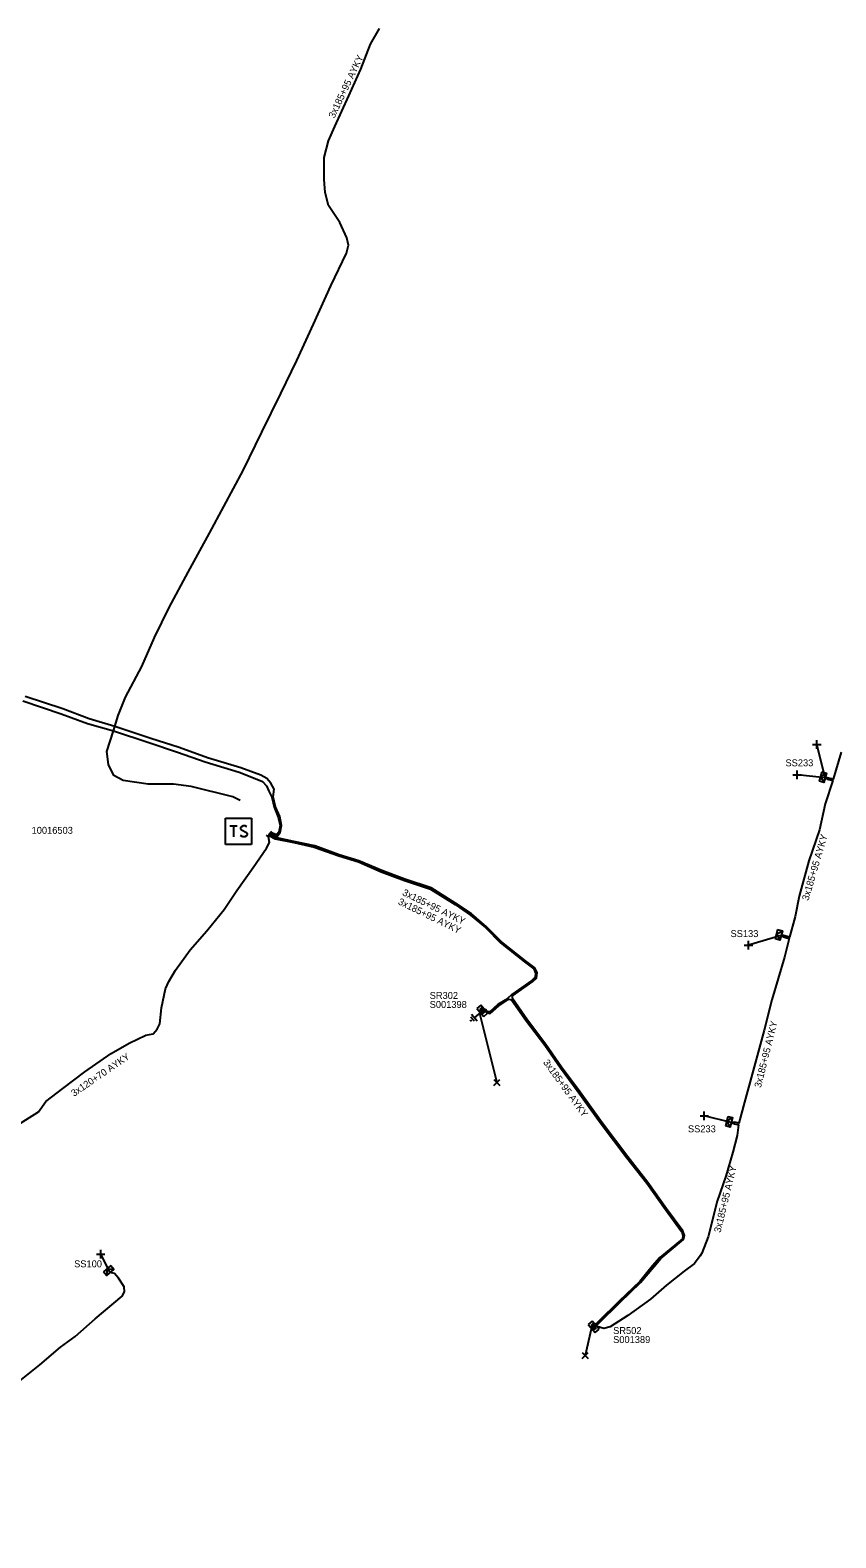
# Model space of a CAD drawing. Extents: x -763093 to -760976, y -1155572 to -1152009.
# Drawn here: x -762242.1 to -762125.9, y -1155258.8 to -1155041.4 of the extents above; entities that cross this region are included whole.
import ezdxf

# ---------------------------------------------------------------- set-up
doc = ezdxf.new("R2010")
doc.units = 0
for name, color, linetype in [('Vrstva 1', 7, 'Continuous'), ('Vrstva 14', 7, 'Continuous'), ('Vrstva 15', 7, 'Continuous'), ('Vrstva 25', 7, 'Continuous'), ('Vrstva 26', 7, 'Continuous'), ('Vrstva 28', 7, 'Continuous'), ('Vrstva 29', 7, 'Continuous'), ('Vrstva 30', 7, 'Continuous'), ('Vrstva 31', 7, 'Continuous'), ('Vrstva 33', 7, 'Continuous'), ('Vrstva 34', 7, 'Continuous'), ('Vrstva 5', 7, 'Continuous'), ('Vrstva 59', 7, 'Continuous'), ('Vrstva 6', 7, 'Continuous'), ('Vrstva 8', 7, 'Continuous'), ('Vrstva 9', 7, 'Continuous')]:
    doc.layers.add(name, color=color, linetype=linetype)

# ---------------------------------------------------------------- blocks, each defined once
blk = doc.blocks.new('NN800')
at = {"layer": 'Vrstva 1'}
for points in [[(-0.44, 0.44), (0.44, -0.44)], [(-0.44, -0.44), (0.44, 0.44)]]:
    blk.add_lwpolyline(points, dxfattribs=at)
blk = doc.blocks.new('NN620')
at = {"layer": 'Vrstva 8'}
for points in [[(0.75, 0), (-0.75, 0)], [(-0.75, 0), (-0.75, -0.75)], [(0.75, -0.75), (0.75, 0)], [(-0.75, -0.75), (0.75, -0.75)], [(0.37, -0.18), (-0.38, -0.18)], [(-0.38, -0.18), (-0.38, -0.56)], [(-0.38, -0.56), (0.37, -0.56)], [(0.32, -0.23), (-0.33, -0.23)], [(-0.33, -0.23), (-0.33, -0.51)], [(-0.33, -0.51), (0.32, -0.51)], [(0.27, -0.27), (-0.28, -0.27)], [(-0.28, -0.27), (-0.28, -0.46)], [(-0.28, -0.46), (0.27, -0.46)], [(0.23, -0.32), (-0.23, -0.32)], [(-0.23, -0.32), (-0.23, -0.42)], [(-0.23, -0.42), (0.23, -0.42)], [(-0.19, -0.37), (0.19, -0.37)], [(0.23, -0.42), (0.23, -0.32)], [(0.27, -0.46), (0.27, -0.27)], [(0.32, -0.51), (0.32, -0.23)], [(0.37, -0.56), (0.37, -0.18)]]:
    blk.add_lwpolyline(points, dxfattribs=at)
blk = doc.blocks.new('NN630')
at = {"layer": 'Vrstva 9'}
for points in [[(0, -0.7), (-0.7, 0)], [(-0.7, -0.7), (-0.7, 0), (0.7, 0), (0.7, -0.7)], [(-0.7, -0.7), (0.7, -0.7)], [(0, -0.7), (0.7, 0)]]:
    blk.add_lwpolyline(points, dxfattribs=at)
blk = doc.blocks.new('NN810')
at = {"layer": 'Vrstva 14'}
for points in [[(0.63, -1.89), (-0.62, -1.89)], [(0, -0.64), (0, -1.89)], [(0.39, -2.2), (-0.4, -2.2)], [(0, -2.52), (-0.12, -2.52)], [(0.14, -2.52), (0, -2.52)]]:
    blk.add_lwpolyline(points, dxfattribs=at)
blk = doc.blocks.new('NN640')
at = {"layer": 'Vrstva 6'}
for points in [[(-1.89, 1.89), (1.89, 1.89)], [(-1.89, -1.89), (-1.89, 1.89)], [(-1.26, 0.79), (-0.22, 0.79)], [(-0.73, 0.79), (-0.73, -0.79)], [(1.2, 0.66), (0.94, 0.79), (0.66, 0.79), (0.41, 0.66), (0.28, 0.47), (0.28, 0.41), (0.41, 0.22), (1.13, -0.16), (1.26, -0.32), (1.26, -0.47), (1.13, -0.66), (0.91, -0.79), (0.63, -0.79), (0.5, -0.73), (0.28, -0.6)], [(1.89, 1.89), (1.89, -1.89)], [(1.89, -1.89), (-1.89, -1.89)]]:
    blk.add_lwpolyline(points, dxfattribs=at)

msp = doc.modelspace()

# ---------------------------------------------------------------- linework, layer by layer
at = {"layer": 'Vrstva 5'}
for points in [[(-762211.82, -1155152.47), (-762212.89, -1155151.97), (-762218.88, -1155150.49), (-762221.47, -1155150.15), (-762225.1, -1155150.14), (-762228.69, -1155149.59), (-762230.04, -1155148.88), (-762230.84, -1155147.3), (-762231.04, -1155145.45), (-762230.08, -1155142.45), (-762229.93, -1155141.84), (-762229.45, -1155140.25), (-762228.38, -1155137.61), (-762226, -1155133.18), (-762224.2, -1155128.99), (-762222.06, -1155124.69), (-762219.32, -1155119.56), (-762216.24, -1155113.95), (-762214.17, -1155110.1), (-762211.4, -1155104.92), (-762208.69, -1155099.41), (-762205.98, -1155093.83), (-762203.67, -1155089.06), (-762201.24, -1155083.82), (-762198.77, -1155078.31), (-762196.49, -1155073.58), (-762196.24, -1155072.42), (-762196.48, -1155071.38), (-762197.47, -1155069.16), (-762199.12, -1155066.71), (-762199.59, -1155064.85), (-762199.74, -1155062.95), (-762199.71, -1155059.79), (-762199.09, -1155057.42), (-762198.17, -1155055.31), (-762196.17, -1155050.9), (-762194.45, -1155047.06), (-762193.03, -1155043.48), (-762191.74, -1155041.22)], [(-762243.18, -1155138.13), (-762237.64, -1155139.99), (-762233.83, -1155141.41), (-762230.08, -1155142.45), (-762225, -1155144.14), (-762220.89, -1155145.51), (-762216.86, -1155146.94), (-762212, -1155148.43), (-762209.19, -1155149.49), (-762208.61, -1155149.77), (-762208.04, -1155150.37), (-762207.68, -1155151.13), (-762207.26, -1155152.02), (-762206.92, -1155153.46), (-762206.34, -1155154.87), (-762206.06, -1155156.11), (-762206.25, -1155157.04), (-762206.6, -1155157.46), (-762207.18, -1155157.18), (-762207.42, -1155156.94)], [(-762207.57, -1155157.07), (-762207.33, -1155157.32), (-762206.54, -1155157.71), (-762206.07, -1155157.12), (-762205.86, -1155156.11), (-762206.14, -1155154.81), (-762206.72, -1155153.4), (-762207.06, -1155151.98), (-762206.95, -1155150.86), (-762207.4, -1155150.01), (-762208, -1155149.34), (-762208.87, -1155148.82), (-762211.76, -1155147.78), (-762216.57, -1155146.33), (-762220.62, -1155144.84), (-762224.71, -1155143.54), (-762229.93, -1155141.84), (-762233.63, -1155140.74), (-762237.43, -1155139.29), (-762242.84, -1155137.5)], [(-762125.19, -1155145.52), (-762126.31, -1155149.4), (-762127.13, -1155149.21), (-762127.47, -1155149.22), (-762127.18, -1155149.4), (-762126.37, -1155149.6), (-762127.47, -1155152.97), (-762128.3, -1155156.7), (-762129.84, -1155161.17), (-762131.25, -1155166.26), (-762131.81, -1155169.22), (-762132.62, -1155172.18), (-762133.5, -1155171.95), (-762133.85, -1155171.95), (-762133.54, -1155172.15), (-762132.67, -1155172.38), (-762133.34, -1155175.08), (-762135.18, -1155181.21), (-762136.26, -1155185.61), (-762137.85, -1155191.4), (-762139.1, -1155196), (-762139.94, -1155199.02), (-762140.51, -1155198.87), (-762141.03, -1155198.89), (-762140.54, -1155199.08), (-762139.98, -1155199.22), (-762140.18, -1155200.76), (-762140.81, -1155203.17), (-762141.81, -1155206.65), (-762143.06, -1155210.25), (-762144.35, -1155215.4), (-762145.25, -1155217.74), (-762145.5, -1155218.13), (-762146.34, -1155219.24), (-762147.84, -1155220.33), (-762150.37, -1155222.34), (-762152.68, -1155224.37), (-762155.93, -1155226.71), (-762158.5, -1155228.35), (-762159.41, -1155228.61), (-762160.34, -1155228.32)], [(-762245.5, -1155200.25), (-762240.9, -1155197.35), (-762239.87, -1155195.89), (-762237.41, -1155193.99), (-762234.23, -1155191.62), (-762230.44, -1155188.98), (-762227.83, -1155187.46), (-762225.42, -1155186.31), (-762224.4, -1155186.11), (-762223.79, -1155185.45), (-762223.4, -1155184.68), (-762223.2, -1155182.37), (-762222.6, -1155179.64), (-762222.11, -1155178.59), (-762221.16, -1155176.93), (-762219.05, -1155174), (-762216.63, -1155171.27), (-762214.16, -1155168.19), (-762212.34, -1155165.48), (-762209.95, -1155162.16), (-762208.03, -1155159.36), (-762207.61, -1155158.56), (-762207.75, -1155157.74), (-762208.02, -1155157.47)], [(-762207.8, -1155157.41), (-762207.61, -1155157.6), (-762206.77, -1155158.03), (-762204.12, -1155158.55), (-762201.15, -1155159.22), (-762197.63, -1155160.48), (-762194.77, -1155161.35), (-762191.49, -1155162.77), (-762188.14, -1155164.03), (-762184.39, -1155165.25), (-762180.83, -1155167.5), (-762178.61, -1155169), (-762176.48, -1155170.82), (-762174.3, -1155173.01), (-762170.83, -1155175.76), (-762169.49, -1155176.75), (-762169.23, -1155177.36), (-762169.31, -1155177.98), (-762169.77, -1155178.43), (-762172.66, -1155180.45), (-762173.28, -1155181.03), (-762173.28, -1155181.06), (-762174.67, -1155181.91), (-762175.86, -1155182.96), (-762176.2, -1155182.89), (-762176.53, -1155182.55)], [(-762160.47, -1155228.15), (-762160.13, -1155227.85), (-762157.04, -1155224.81), (-762154.09, -1155221.96), (-762152.21, -1155219.69), (-762151.19, -1155218.53), (-762147.9, -1155215.75), (-762147.79, -1155215.22), (-762148.02, -1155214.54), (-762150.36, -1155211.33), (-762153.05, -1155207.55), (-762155.92, -1155203.87), (-762159.64, -1155198.97), (-762163.07, -1155194.18), (-762165.48, -1155190.93), (-762167.77, -1155187.65), (-762170.39, -1155184.16), (-762172.57, -1155181.05), (-762172.59, -1155180.64), (-762169.65, -1155178.59), (-762169.13, -1155178.08), (-762169.03, -1155177.34), (-762169.33, -1155176.63), (-762170.71, -1155175.6), (-762174.16, -1155172.87), (-762176.34, -1155170.68), (-762178.49, -1155168.84), (-762180.73, -1155167.34), (-762184.31, -1155165.07), (-762188.08, -1155163.85), (-762191.41, -1155162.59), (-762194.71, -1155161.17), (-762197.57, -1155160.3), (-762201.09, -1155159.02), (-762204.1, -1155158.38), (-762206.72, -1155157.84), (-762207.47, -1155157.46), (-762207.69, -1155157.24)], [(-762176.68, -1155182.69), (-762176.3, -1155183.07), (-762175.8, -1155183.18), (-762174.55, -1155182.07), (-762173.09, -1155181.14), (-762172.7, -1155181.21), (-762170.55, -1155184.28), (-762167.93, -1155187.77), (-762165.64, -1155191.05), (-762163.23, -1155194.3), (-762159.8, -1155199.09), (-762156.08, -1155203.99), (-762153.21, -1155207.67), (-762150.52, -1155211.45), (-762148.2, -1155214.64), (-762148.17, -1155214.63), (-762147.99, -1155215.24), (-762148.08, -1155215.65), (-762148.06, -1155215.67), (-762151.33, -1155218.39), (-762152.37, -1155219.55), (-762154.23, -1155221.82), (-762157.18, -1155224.67), (-762160.27, -1155227.71), (-762160.58, -1155227.99)], [(-762272.4, -1155253.44), (-762271.63, -1155253.95), (-762271.29, -1155255.29), (-762271.06, -1155256.16), (-762269.97, -1155258.75), (-762269.45, -1155258.78), (-762268.73, -1155258.38), (-762266.51, -1155256.3), (-762263.78, -1155253.74), (-762260.83, -1155251.11), (-762256.92, -1155247.7), (-762252.25, -1155243.71), (-762248.55, -1155240.24), (-762244.55, -1155236.91), (-762240.7, -1155233.83), (-762237.74, -1155231.29), (-762235.63, -1155229.77), (-762232.76, -1155227.19), (-762228.83, -1155223.92), (-762228.52, -1155223.3), (-762228.57, -1155222.61), (-762229.37, -1155221.34), (-762229.97, -1155220.67), (-762230.57, -1155220.52)]]:
    msp.add_lwpolyline(points, dxfattribs=at)
at = {"layer": 'Vrstva 59'}
for points in [[(-762127.47, -1155149.22), (-762128.7, -1155144.39)], [(-762127.47, -1155149.22), (-762131.54, -1155148.78)], [(-762133.85, -1155171.95), (-762138.52, -1155173.35)], [(-762177.31, -1155183.15), (-762174.84, -1155193.13)], [(-762141.03, -1155198.89), (-762144.91, -1155197.93)], [(-762230.57, -1155220.52), (-762231.95, -1155217.88)], [(-762161.25, -1155228.69), (-762162.09, -1155232.51)]]:
    msp.add_lwpolyline(points, dxfattribs=at)

# ---------------------------------------------------------------- block references
at = {"layer": 'Vrstva 15', "rotation": -49.070186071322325}
msp.add_blockref('NN810', (-762176.65, -1155182.57), dxfattribs=at)
at = {"layer": 'Vrstva 25'}
msp.add_blockref('NN640', (-762212.07, -1155156.94), dxfattribs=at)
at = {"layer": 'Vrstva 28'}
for p, rotation in [((-762176.65, -1155182.57), -49.070186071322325), ((-762160.58, -1155228.12), -49.25688334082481)]:
    msp.add_blockref('NN620', p, dxfattribs=dict(at, rotation=rotation))
at = {"layer": 'Vrstva 31'}
for p, rotation in [((-762127.47, -1155149.22), -106.45380845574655), ((-762133.85, -1155171.95), -105.60688334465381), ((-762141.03, -1155198.89), -103.95816112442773), ((-762230.57, -1155220.52), -139.07278892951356)]:
    msp.add_blockref('NN630', p, dxfattribs=dict(at, rotation=rotation))
at = {"layer": 'Vrstva 34'}
for p, rotation in [((-762128.7, -1155144.4), 44.99999995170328), ((-762131.54, -1155148.78), 45), ((-762138.52, -1155173.35), 45.00000009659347), ((-762144.91, -1155197.93), 45), ((-762231.95, -1155217.88), 45)]:
    msp.add_blockref('NN800', p, dxfattribs=dict(at, rotation=rotation))
for p in [(-762174.84, -1155193.13), (-762162.09, -1155232.51)]:
    msp.add_blockref('NN800', p, dxfattribs=at)

# ---------------------------------------------------------------- texts
at = {"layer": 'Vrstva 26'}
msp.add_text('10016503', height=1, dxfattribs=at).set_placement((-762241.91, -1155157.29))
at = {"layer": 'Vrstva 29'}
for s, p in [('S001398', (-762184.51, -1155182.39)), ('S001389', (-762158.06, -1155230.7))]:
    msp.add_text(s, height=1, dxfattribs=at).set_placement(p)
at = {"layer": 'Vrstva 30'}
for s, p in [('SR302', (-762184.51, -1155181.09)), ('SR502', (-762158.06, -1155229.4))]:
    msp.add_text(s, height=1, dxfattribs=at).set_placement(p)
at = {"layer": 'Vrstva 33'}
for s, p in [('SS233', (-762133.21, -1155147.56)), ('SS133', (-762141.13, -1155172.18)), ('SS233', (-762147.27, -1155200.32)), ('SS100', (-762235.78, -1155219.78))]:
    msp.add_text(s, height=1, dxfattribs=at).set_placement(p)
at = {"layer": 'Vrstva 6'}
for s, rotation, p in [('3x185+95 AYKY', 64.571, (-762198.26, -1155054.22)), ('3x185+95 AYKY', 73.677, (-762129.9, -1155166.99)), ('3x185+95 AYKY', 333.904, (-762188.54, -1155166.09)), ('3x185+95 AYKY', 333.904, (-762189.16, -1155167.4)), ('3x185+95 AYKY', 75.848, (-762136.76, -1155193.97)), ('3x120+70 AYKY', 34.413, (-762235.79, -1155195.22)), ('3x185+95 AYKY', 306.022, (-762168.21, -1155190.26)), ('3x185+95 AYKY', 76.234, (-762142.58, -1155214.85))]:
    msp.add_text(s, height=1, rotation=rotation, dxfattribs=at).set_placement(p)

doc.saveas('drawing.dxf')
